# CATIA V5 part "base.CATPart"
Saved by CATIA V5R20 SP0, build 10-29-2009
Part number: Part1
Bounding box of the stored display mesh (mm): x -8.62 to 108.62, y 0 to 170, z -40 to 79
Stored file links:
  C:\Users\khanm\Downloads\Catia Project\Catia Project\base.CATPart
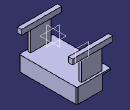
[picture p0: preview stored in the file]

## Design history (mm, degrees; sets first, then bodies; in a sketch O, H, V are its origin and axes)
Body1 (main body)
  Sketch1 on xy-plane, origin (0, 0, 0), H (1, 0, 0), V (0, 1, 0)
    line L1 (3, 0) -> (97, 0)
    point P1 (100, 0)
    line L2 (0, 3) -> (0, 17)
    point P2 (0, 20)
    line L3 (3, 20) -> (40, 20)
    point P3 (40, 20)
    line L4 (100, 3) -> (100, 167)
    point P4 (100, 170)
    line L5 (97, 170) -> (3, 170)
    point P5 (0, 170)
    line L6 (0, 167) -> (0, 153)
    point P6 (0, 150)
    line L7 (3, 150) -> (40, 150)
    point P7 (40, 150)
    line L8 (40, 150) -> (40, 20)
    arc A1 centre (3, 17) radius 3 from (3, 20) to (0, 17) ccw
    arc A2 centre (3, 3) radius 3 from (0, 3) to (3, 0) ccw
    arc A3 centre (3, 167) radius 3 from (3, 170) to (0, 167) ccw
    arc A4 centre (3, 153) radius 3 from (0, 153) to (3, 150) ccw
    arc A5 centre (97, 167) radius 3 from (100, 167) to (97, 170) ccw
    arc A6 centre (97, 3) radius 3 from (97, 0) to (100, 3) ccw
    point P20 (100, 3)
    point P21 (97, 0)
    point P22 (97, 0)
    point P23 (100, 3)
    radius A1 = 3
    radius A2 = 3
    radius A3 = 3
    radius A4 = 3
    radius A5 = 3
    radius A6 = 3
    distance P4 P5 = 100
    distance P5 P6 = 20
    distance P6 P7 = 40
    distance P1 P4 = 170
    distance O P1 = 100
    distance P2 P3 = 40
    distance O P2 = 20
    horizontal: L1 H, L3 H, L5 H, L7 H
    vertical: L2 V, L4 V, L6 V, L8 V
    tangency: A1 L2, A1 L3, A2 L1, A2 L2, A3 L5, A3 L6, A4 L7, A4 L6, A5 L4, A5 L5, A6 L1, A6 L4
    coincidence: A6 P20, A6 P21, L4 P23, L1 P22, P20 P23, P21 P22
  Pad1: profile Sketch1, direction (0, 0, 1), length 4
  Sketch2 on end face of Pad1, origin (0, 0, 4), H (1, 0, 0), V (0, 1, 0)
    point P1 (49.995, 160.005)
    line L1 (80.1, 163.76) -> (80.1, 156.25)
    line L2 (80.1, 156.25) -> (19.89, 156.25)
    line L3 (19.89, 156.25) -> (19.89, 163.76)
    line L4 (19.89, 163.76) -> (80.1, 163.76)
    point P2 (80.1, 163.76)
    point P3 (80.1, 156.25)
    point P4 (19.89, 156.25)
    point P5 (19.89, 163.76)
    reference projected line E1 (97, 170) -> (3, 170) from edge [face of Pad1 from Sketch1.L5 | end face of Pad1]
    reference projected line E2 (0, 167) -> (0, 153) from edge [face of Pad1 from Sketch1.L6 | end face of Pad1]
    construction line L5 (-54.737, 85) -> (195.1994, 85)
    point P8 (19.89, 13.75)
    point P9 (80.1, 13.75)
    line L6 (80.1, 13.75) -> (19.89, 13.75)
    point P10 (19.89, 6.24)
    line L7 (19.89, 13.75) -> (19.89, 6.24)
    point P11 (80.1, 6.24)
    line L8 (19.89, 6.24) -> (80.1, 6.24)
    line L9 (80.1, 6.24) -> (80.1, 13.75)
    length L2 = 60.21
    length L3 = 7.51
    distance E1 L4 = 6.24
    distance E2 L3 = 19.89
    distance L5 H = 85
    vertical: L1 V, L3 V
    horizontal: L2 H, L4 H, L5 H
    equidistance: L1 L3 P1, L2 L4 P1
    symmetry: P4 P8 L5, P3 P9 L5, L2 L6 L5, P5 P10 L5, L3 L7 L5, P2 P11 L5, L4 L8 L5, L1 L9 L5
  Pad2: profile Sketch2, direction (0, 0, 1), length 60
  Sketch3 on end face of Pad2, origin (0, 0, 64), H (1, 0, 0), V (0, 1, 0)
    point P1 (50, 160.005)
    line L1 (108.62, 166.07) -> (108.62, 153.94)
    line L2 (108.62, 153.94) -> (-8.62, 153.94)
    line L3 (-8.62, 153.94) -> (-8.62, 166.07)
    line L4 (-8.62, 166.07) -> (108.62, 166.07)
    reference projected line E1 (19.89, 163.76) -> (19.89, 156.25) from edge [face of Pad2 from Sketch2.L3 | end face of Pad2]
    reference projected line E2 (80.1, 163.76) -> (19.89, 163.76) from edge [face of Pad2 from Sketch2.L4 | end face of Pad2]
    reference projected line E3 (19.89, 156.25) -> (80.1, 156.25) from edge [face of Pad2 from Sketch2.L2 | end face of Pad2]
    length L4 = 117.24
    distance E1 L3 = 28.51
    distance L4 E2 = 2.31
    distance E3 L2 = 2.31
    vertical: L1 V, L3 V
    horizontal: L2 H, L4 H
    equidistance: L1 L3 P1, L2 L4 P1
  Pad3: profile Sketch3, direction (0, 0, 1), length 15
  Plane1: type Offset, RefPlane zx-plane, Offset 85
  Mirror1: of Pad3, about Plane1
  Sketch4 on start face of Pad1, origin (0, 0, 0), H (1, 0, 0), V (0, -1, 0)
    line L1 (40, -20) -> (40, 0)
    point P1 (40, 0)
    line L2 (40, 0) -> (97, 0)
    line L3 (100, -167) -> (100, -3)
    line L4 (40, -150) -> (40, -170)
    point P3 (40, -150)
    line L5 (40, -170) -> (97, -170)
    line L6 (40, -20) -> (82.31, -20)
    line L7 (82.31, -20) -> (82.31, -150)
    line L8 (40, -150) -> (82.31, -150)
    reference projected line E1 (3, 0) -> (97, 0) from edge [start face of Pad1 | face of Pad1 from Sketch1.L1]
    reference projected line E2 (97, -170) -> (3, -170) from edge [start face of Pad1 | face of Pad1 from Sketch1.L5]
    reference projected line E3 (100, -3) -> (100, -167) from edge [start face of Pad1 | face of Pad1 from Sketch1.L4]
    reference projected line E4 (40, -20) -> (3, -20) from edge [start face of Pad1 | face of Pad1 from Sketch1.L3]
    reference projected line E5 (3, -150) -> (40, -150) from edge [start face of Pad1 | face of Pad1 from Sketch1.L7]
    arc A1 centre (97, -3) radius 3 from (100, -3) to (97, 0) ccw
    arc A2 centre (97, -167) radius 3 from (97, -170) to (100, -167) ccw
    point P9 (97, -170)
    point P10 (100, -167)
    point P11 (97, -170)
    point P12 (100, -167)
    distance L7 L3 = 17.69
    length L6 = 42.31
    radius A1 = 3
    radius A2 = 3
    coincidence: P1 H, P3 L1, L2 E1, L5 E2, L3 E3, L6 E4, L8 E5, A2 P9, A2 P10, L3 P12, L5 P11, P9 P11, P10 P12
    vertical: L1 V, L3 V, L4 V, L7 V
    horizontal: L2 H, L5 H, L6 H, L8 H
    tangency: A1 L3, A1 L2, A2 L5, A2 L3
  Pad4: profile Sketch4, direction (0, 0, -1), length 40
  Sketch5 on face of Pad1 from Sketch1.L8, origin (40, 0, 0), H (0, -1, 0), V (0, 0, 1)
    point P1 (-85, 2)
    line L1 (-20, 4) -> (-20, 0)
    line L2 (-20, 0) -> (-150, 0)
    line L3 (-150, 0) -> (-150, 4)
    line L4 (-150, 4) -> (-20, 4)
    reference projected line E1 (-150, 4) -> (-20, 4) from edge [face of Pad1 from Sketch1.L8 | end face of Pad1]
    reference projected line E2 (-150, 0) -> (-20, 0) from edge [start face of Pad1 | face of Pad1 from Sketch1.L8]
    reference projected line E3 (-150, 0) -> (-150, 4) from edge [face of Pad1 from Sketch1.L7 | face of Pad1 from Sketch1.A4]
    reference projected line E4 (-20, 0) -> (-20, 4) from edge [face of Pad1 from Sketch1.A1 | face of Pad1 from Sketch1.L3]
    vertical: L1 V, L3 V
    horizontal: L2 H, L4 H
    equidistance: L1 L3 P1, L2 L4 P1
    coincidence: L4 E1, E2 L2, L3 E3, L1 E4
  Pad5: profile Sketch5, direction (-1, 0, 0), length 40
  Sketch6 on end face of Pad5, origin (0, 0, 0), H (0, -1, 0), V (0, 0, 1)
    point P1 (-149.8923, 2)
    line L1 (-146.7846, 4) -> (-146.7846, 0)
    line L2 (-146.7846, 0) -> (-153, 0)
    line L3 (-153, 0) -> (-153, 4)
    line L4 (-153, 4) -> (-146.7846, 4)
    point P3 (-146.7846, 0)
    reference projected line E1 (-153, 0) -> (-153, 4) from edge [face of Pad1 from Sketch1.A4 | face of Pad1 from Sketch1.L6]
    reference projected line E2 (-153, 4) -> (-150, 4) from edge [face of Pad1 from Sketch1.A4 | face of Pad5]
    reference projected line E3 (-167, 0) -> (-153, 0) from edge [start face of Pad1 | face of Pad1 from Sketch1.L6]
    vertical: L1 V, L3 V
    horizontal: L2 H, L4 H
    equidistance: L1 L3 P1, L2 L4 P1
    coincidence: P3 H, L3 E1, L4 E2, L2 E3
  Pad6: profile Sketch6, direction (-1, 0, 0), up to the existing solid (limit type 2)
  Mirror2: of Pad6, about Plane1
  Sketch7 on face of Pad4 from Sketch4.L7, origin (82.31, 0, 0), H (0, -1, 0), V (0, 0, 1)
    point P1 (-150, 0)
    line L1 (-150, 0) -> (-20, 0)
    line L2 (-20, 0) -> (-20, -40)
    line L3 (-20, -40) -> (-150, -40)
    line L4 (-150, -40) -> (-150, 0)
    reference projected line E1 (-150, 0) -> (-150, -40) from edge [face of Pad4 from Sketch4.L4 | face of Pad4 from Sketch4.L8]
    reference projected line E2 (-3, 0) -> (-17, 0) from edge [face of Mirror2 | face of Pad6]
    reference projected line E4 (-20, -40) -> (-150, -40) from edge [face of Pad4 from Sketch4.L7 | end face of Pad4]
    reference projected line E5 (-20, 0) -> (-20, -40) from edge [face of Pad4 from Sketch4.L6 | face of Pad4 from Sketch4.L1]
    coincidence: P1 H, L4 E1, L1 E2, L3 E4, L2 E5
    horizontal: L1 H, L3 H
    vertical: L2 V, L4 V
  Pad7: profile Sketch7, direction (-1, 0, 0), length 10
  Sketch8 on face of Pad4 from Sketch4.L4, origin (40, 0, 0), H (0, -1, 0), V (0, 0, 1)
    point P1 (-170, 0)
    line L1 (-170, 0) -> (-150, 0)
    line L2 (-150, 0) -> (-150, -40)
    line L3 (-150, -40) -> (-170, -40)
    line L4 (-170, -40) -> (-170, 0)
    reference projected line E1 (-170, 0) -> (-170, -40) from edge [face of Pad4 | face of Pad4 from Sketch4.L4]
    reference projected line E2 (-150, 0) -> (-150, -40) from edge [face of Pad4 from Sketch4.L4 | face of Pad4 from Sketch4.L8]
    reference projected line E3 (-3, 0) -> (-17, 0) from edge [face of Mirror2 | face of Pad6]
    reference projected line E5 (-150, -40) -> (-170, -40) from edge [face of Pad4 from Sketch4.L4 | end face of Pad4]
    coincidence: P1 H, E1 L4, E2 L2, L1 E3, L3 E5
    horizontal: L1 H, L3 H
    vertical: L2 V, L4 V
  Pad8: profile Sketch8, direction (-1, 0, 0), length 15
  Mirror3: of Pad8, about Plane1
  Sketch9 on face of Mirror3, origin (0, 0, -40), H (1, 0, 0), V (0, -1, 0)
    line L1 (32.73, -158.5) -> (80.73, -158.5)
    line L2 (80.73, -158.5) -> (80.73, -160.5)
    line L3 (80.73, -160.5) -> (32.73, -160.5)
    line L4 (32.73, -160.5) -> (32.73, -158.5)
    reference projected line E1 (25, -170) -> (25, -150) from edge [face of Mirror3 | end face of Pad8]
    reference projected line E2 (82.31, -150) -> (40, -150) from edge [face of Pad8 | face of Mirror3]
    length L3 = 48
    length L4 = 2
    distance E1 L4 = 7.73
    distance E2 L1 = 8.5
    horizontal: L1 H, L3 H
    vertical: L2 V, L4 V
  Pocket1: profile Sketch9, direction (0, 0, 1), length 10
  Mirror4: of Pocket1, about Plane1
  Sketch10 on end face of Pad7, origin (72.31, 0, 0), H (0, -1, 0), V (0, 0, 1)
    point P1 (-85.1412, -19.0868)
    line L1 (-77.7622, -11.7935) -> (-77.7622, -26.3801)
    line L2 (-77.7622, -26.3801) -> (-92.5202, -26.3801)
    line L3 (-92.5202, -26.3801) -> (-92.5202, -11.7935)
    line L4 (-92.5202, -11.7935) -> (-77.7622, -11.7935)
  Pad9: profile Sketch10, direction (-1, 0, 0), length 65
  Sketch11 on end face of Pad7, origin (72.31, 0, 0), H (0, -1, 0), V (0, 0, 1)
    point P1 (-150, 0)
    line L1 (-150, 0) -> (-20, 0)
    line L2 (-20, 0) -> (-20, -40)
    line L3 (-20, -40) -> (-150, -40)
    line L4 (-150, -40) -> (-150, 0)
    reference projected line E1 (-150, 0) -> (-150, -40) from edge [face of Pad4 from Sketch4.L4 | face of Pad4 from Sketch4.L8]
    reference projected line E2 (-3, 0) -> (-17, 0) from edge [face of Mirror2 | face of Pad6]
    reference projected line E4 (-20, -40) -> (-150, -40) from edge [face of Pad4 from Sketch4.L7 | end face of Pad4]
    reference projected line E5 (-20, 0) -> (-20, -40) from edge [face of Pad4 from Sketch4.L6 | face of Pad4 from Sketch4.L1]
    coincidence: P1 H, L4 E1, L1 E2, L3 E4, L2 E5
    horizontal: L1 H, L3 H
    vertical: L2 V, L4 V
  Pad10: profile Sketch11, direction (-1, 0, 0), length 10
  Sketch12 on end face of Pad10, origin (62.31, 0, 0), H (0, -1, 0), V (0, 0, 1)
    point P1 (-150, 0)
    line L1 (-150, 0) -> (-20, 0)
    line L2 (-20, 0) -> (-20, -40)
    line L3 (-20, -40) -> (-150, -40)
    line L4 (-150, -40) -> (-150, 0)
    reference projected line E1 (-150, 0) -> (-150, -40) from edge [face of Pad4 from Sketch4.L4 | face of Pad4 from Sketch4.L8]
    reference projected line E2 (-3, 0) -> (-17, 0) from edge [face of Mirror2 | face of Pad6]
    reference projected line E4 (-20, -40) -> (-150, -40) from edge [face of Pad4 from Sketch4.L7 | end face of Pad4]
    reference projected line E5 (-20, 0) -> (-20, -40) from edge [face of Pad4 from Sketch4.L6 | face of Pad4 from Sketch4.L1]
    coincidence: P1 H, L4 E1, L1 E2, L3 E4, L2 E5
    horizontal: L1 H, L3 H
    vertical: L2 V, L4 V
  Pad11: profile Sketch12, direction (-1, 0, 0), length 10
Current feature: Pad9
